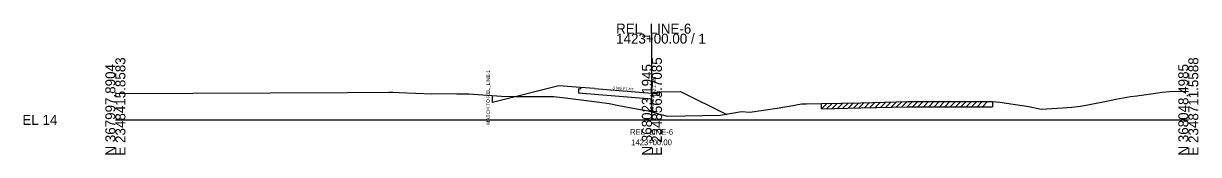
# Model space of a CAD drawing. Extents: x -26 to 403, y -10 to 6565.
# Drawn here: x -25.7 to 302.8, y 3990.3 to 4026.9 of the extents above; entities that cross this region are included whole.
import ezdxf

# ---------------------------------------------------------------- set-up
doc = ezdxf.new("R2010")
doc.units = 0
for name, color, linetype in [('RD_GPK_XS_Cell', 7, 'Continuous'), ('RD_XS_Base', 7, 'Continuous'), ('RD_XS_CurbBase', 7, 'Continuous'), ('RD_XS_CurbFront', 7, 'Continuous'), ('RD_XS_CurbTop', 7, 'Continuous'), ('RD_XS_EarthShd', 7, 'Continuous'), ('RD_XS_ExGround', 7, 'Continuous'), ('RD_XS_ExPaveRet', 7, 'Continuous'), ('RD_XS_Pave', 7, 'Continuous'), ('RD_XS_PaveShd', 7, 'Continuous'), ('RD_XS_TieSlope', 7, 'Continuous'), ('RD_XS_TX_Elev_EX', 7, 'Continuous'), ('RD_XS_TX_Elev_PR', 7, 'Continuous'), ('RD_XS_TX_MatchLine', 7, 'Continuous'), ('RD_XS_TX_Slope', 7, 'Continuous'), ('RD_XS_TX_Station', 7, 'Continuous'), ('RD_XS_TX_TOC', 7, 'Continuous')]:
    doc.layers.add(name, color=color, linetype=linetype)

msp = doc.modelspace()

# ---------------------------------------------------------------- linework, layer by layer
at = {"layer": 'RD_GPK_XS_Cell'}
for p, q in [((150, 4000), (150, 4024.11)), ((0, 4000), (150, 4000)), ((150, 4000), (300, 4000))]:
    msp.add_line(p, q, dxfattribs=at)
at = {"layer": 'RD_XS_Base'}
for p, q in [((130, 4008.6), (129.5, 4008.64)), ((129.5, 4008.64), (129.5, 4007.45)), ((130, 4009.05), (130, 4008.6)), ((150, 4005.81), (129.5, 4007.45))]:
    msp.add_line(p, q, dxfattribs=at)
at = {"layer": 'RD_XS_CurbBase'}
for p, q in [((151.5, 4006.85), (150, 4006.93)), ((150, 4005.81), (150, 4006.93)), ((152, 4006.85), (151.5, 4006.85)), ((152, 4007.85), (152, 4006.85))]:
    msp.add_line(p, q, dxfattribs=at)
at = {"layer": 'RD_XS_CurbFront'}
msp.add_line((150, 4006.93), (150, 4007.43), dxfattribs=at)
at = {"layer": 'RD_XS_CurbTop'}
for p, q in [((150, 4007.45), (150, 4007.43)), ((150, 4007.43), (151.42, 4007.35)), ((151.42, 4007.35), (151.5, 4007.85)), ((151.5, 4007.85), (152, 4007.85))]:
    msp.add_line(p, q, dxfattribs=at)
at = {"layer": 'RD_XS_EarthShd'}
for p, q in [((124, 4009.53), (105.4, 4004.88)), ((130, 4009.05), (124, 4009.53)), ((152, 4007.85), (158, 4007.97))]:
    msp.add_line(p, q, dxfattribs=at)
at = {"layer": 'RD_XS_ExGround'}
msp.add_lwpolyline([(0, 4007.39), (64.89, 4007.67), (76.45, 4007.72), (77.5, 4007.7), (79.35, 4007.69), (88.49, 4007.32), (89.32, 4007.35), (95.43, 4007.32), (98.78, 4007.27), (107.98, 4006.6), (110.5, 4006.51), (119.85, 4006.53), (122.59, 4006.53), (126.52, 4006.1), (130.25, 4005.63), (135.36, 4004.96), (138.02, 4004.58), (140.8, 4003.97), (145.73, 4003.05), (149.02, 4002.49), (150, 4002.22), (150.87, 4001.98), (154.3, 4001.03), (169.12, 4001.35), (175.06, 4002.3), (177.42, 4002.17), (185.08, 4003.27), (186.62, 4003.5), (188.38, 4003.82), (191.88, 4004.5), (193.28, 4004.47), (197.41, 4004.53), (208.39, 4004.79), (221.55, 4005.12), (239.06, 4005.11), (245.27, 4005.12), (247.26, 4004.92), (255.4, 4003.69), (258.87, 4002.99), (264.85, 4003.37), (267.46, 4003.5), (269.82, 4003.87), (272.37, 4004.3), (277.56, 4005.34), (278.39, 4005.5), (279.71, 4005.76), (283.84, 4006.5), (285.58, 4006.76), (292.79, 4007.72), (294.73, 4007.97), (300, 4008.04)], dxfattribs=at)
at = {"layer": 'RD_XS_ExPaveRet'}
for p, q in [((207.91, 4003.35), (209.38, 4004.82)), ((209.41, 4003.38), (210.88, 4004.86)), ((210.91, 4003.42), (212.38, 4004.89)), ((212.41, 4003.46), (213.88, 4004.93)), ((213.91, 4003.49), (215.38, 4004.97)), ((215.41, 4003.53), (216.88, 4005)), ((216.91, 4003.57), (218.38, 4005.04)), ((218.41, 4003.6), (219.88, 4005.08)), ((219.91, 4003.64), (221.38, 4005.11)), ((221.41, 4003.68), (222.85, 4005.12)), ((222.91, 4003.68), (224.35, 4005.12)), ((224.41, 4003.68), (225.85, 4005.12)), ((225.91, 4003.68), (227.35, 4005.12)), ((227.41, 4003.68), (228.85, 4005.12)), ((228.91, 4003.68), (230.35, 4005.12)), ((230.41, 4003.68), (231.85, 4005.12)), ((231.91, 4003.68), (233.35, 4005.12)), ((233.41, 4003.68), (234.85, 4005.12)), ((234.91, 4003.68), (236.35, 4005.11)), ((236.41, 4003.68), (237.85, 4005.11)), ((237.91, 4003.68), (239.35, 4005.11)), ((239.41, 4003.68), (240.85, 4005.12)), ((240.91, 4003.68), (242.35, 4005.12)), ((242.41, 4003.68), (243.85, 4005.12)), ((245.27, 4005.12), (245.27, 4003.68)), ((197.41, 4003.09), (198.88, 4004.56)), ((197.41, 4003.09), (197.41, 4004.53)), ((197.41, 4003.09), (208.39, 4003.36)), ((198.91, 4003.13), (200.38, 4004.6)), ((200.41, 4003.16), (201.88, 4004.63)), ((201.91, 4003.2), (203.38, 4004.67)), ((203.41, 4003.24), (204.88, 4004.71)), ((204.91, 4003.27), (206.38, 4004.74)), ((206.41, 4003.31), (207.88, 4004.78)), ((208.39, 4003.36), (221.55, 4003.68)), ((221.55, 4003.68), (239.06, 4003.68)), ((239.06, 4003.68), (245.27, 4003.68))]:
    msp.add_line(p, q, dxfattribs=at)
at = {"layer": 'RD_XS_Pave'}
for p, q in [((134, 4008.73), (150, 4007.45)), ((105.4, 4004.88), (105.4, 4006.79))]:
    msp.add_line(p, q, dxfattribs=at)
at = {"layer": 'RD_XS_PaveShd'}
msp.add_line((134, 4008.73), (130, 4009.05), dxfattribs=at)
at = {"layer": 'RD_XS_TieSlope'}
msp.add_line((158, 4007.97), (170.93, 4001.5), dxfattribs=at)

# ---------------------------------------------------------------- texts
at = {"layer": 'RD_GPK_XS_Cell'}
for s, p in [('REL_LINE-6', (140, 4024.11)), ('1423+00.00 / 1', (140, 4021.31)), ('EL 14', (-26, 3998.6))]:
    msp.add_text(s, height=2.8, dxfattribs=at).set_placement(p)
for s, p in [('N 367997.8904', (0, 3990)), ('E 2348415.8583', (2.8, 3990)), ('N 368023.1945', (150, 3990)), ('E 2348563.7085', (152.8, 3990)), ('N 368048.4985', (300, 3990)), ('E 2348711.5588', (302.8, 3990))]:
    msp.add_text(s, height=2.8, rotation=90, dxfattribs=at).set_placement(p)
at = {"layer": 'RD_XS_TX_Elev_EX'}
msp.add_text('16.22', height=1, rotation=90, dxfattribs=at).set_placement((150.5, 4002.22))
at = {"layer": 'RD_XS_TX_Elev_PR'}
msp.add_text(' 21.45', height=1.2, rotation=90, dxfattribs=at).set_placement((151.2, 4007.45))
at = {"layer": 'RD_XS_TX_MatchLine'}
msp.add_text('MATCH TO REL_LINE-1', height=1, rotation=90, dxfattribs=at).set_placement((104.7, 3998.6))
at = {"layer": 'RD_XS_TX_Slope'}
msp.add_text('0.080 FT./FT.', height=0.75, rotation=355.4291, dxfattribs=at).set_placement((139, 4008.58))
at = {"layer": 'RD_XS_TX_Station'}
for s, p in [('REL_LINE-6', (143.92, 3995.81)), ('1423+00.00', (144.23, 3992.91))]:
    msp.add_text(s, height=1.6, dxfattribs=at).set_placement(p)
at = {"layer": 'RD_XS_TX_TOC'}
msp.add_text('TOCRT', height=0.05, dxfattribs=at).set_placement((151.22, 4007.8))

doc.saveas('drawing.dxf')
